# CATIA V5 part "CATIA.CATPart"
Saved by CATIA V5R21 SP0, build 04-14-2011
Part number: Part1
Bounding box of the stored display mesh (mm): x -76.2 to 76.2, y -75.042 to 75.042, z 0 to 0
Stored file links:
  C:\Users\Orange\Desktop\Sketcher-16\Documents\CATIA.CATPart
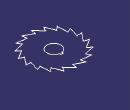
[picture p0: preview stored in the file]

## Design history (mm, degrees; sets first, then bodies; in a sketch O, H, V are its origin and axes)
Body1 (main body)
  Sketch1 on xy-plane, origin (0, 0, 0), H (1, 0, 0), V (0, 1, 0)
    arc A1 centre (0, 0) radius 19.05 from (-3.175, 18.7836) to (3.175, 18.7836) ccw
    line L1 (59.6705, 21.7183) -> (71.6046, 26.0619)
    line L2 (63.5, 0) -> (71.6046, 26.0619)
    line L3 (48.6438, 40.817) -> (58.3726, 48.9804)
    line L4 (59.6705, 21.7183) -> (58.3726, 48.9804)
    line L5 (31.75, 54.9926) -> (38.1, 65.9911)
    line L6 (48.6438, 40.817) -> (38.1, 65.9911)
    line L7 (11.0267, 62.5353) -> (13.232, 75.0424)
    line L8 (31.75, 54.9926) -> (13.232, 75.0424)
    line L9 (-11.0267, 62.5353) -> (-13.232, 75.0424)
    line L10 (11.0267, 62.5353) -> (-13.232, 75.0424)
    line L11 (-31.75, 54.9926) -> (-38.1, 65.9911)
    line L12 (-11.0267, 62.5353) -> (-38.1, 65.9911)
    line L13 (-48.6438, 40.817) -> (-58.3726, 48.9804)
    line L14 (-31.75, 54.9926) -> (-58.3726, 48.9804)
    line L15 (-59.6705, 21.7183) -> (-71.6046, 26.0619)
    line L16 (-48.6438, 40.817) -> (-71.6046, 26.0619)
    line L17 (-63.5, 0) -> (-76.2, 0)
    line L18 (-59.6705, 21.7183) -> (-76.2, 0)
    line L19 (-59.6705, -21.7183) -> (-71.6046, -26.0619)
    line L20 (-63.5, 0) -> (-71.6046, -26.0619)
    line L21 (-48.6438, -40.817) -> (-58.3726, -48.9804)
    line L22 (-59.6705, -21.7183) -> (-58.3726, -48.9804)
    line L23 (-31.75, -54.9926) -> (-38.1, -65.9911)
    line L24 (-48.6438, -40.817) -> (-38.1, -65.9911)
    line L25 (-11.0267, -62.5353) -> (-13.232, -75.0424)
    line L26 (-31.75, -54.9926) -> (-13.232, -75.0424)
    line L27 (11.0267, -62.5353) -> (13.232, -75.0424)
    line L28 (-11.0267, -62.5353) -> (13.232, -75.0424)
    line L29 (31.75, -54.9926) -> (38.1, -65.9911)
    line L30 (11.0267, -62.5353) -> (38.1, -65.9911)
    line L31 (48.6438, -40.817) -> (58.3726, -48.9804)
    line L32 (31.75, -54.9926) -> (58.3726, -48.9804)
    line L33 (59.6705, -21.7183) -> (71.6046, -26.0619)
    line L34 (48.6438, -40.817) -> (71.6046, -26.0619)
    line L35 (63.5, 0) -> (76.2, 0)
    line L36 (59.6705, -21.7183) -> (76.2, 0)
    line L37 (-3.175, 22.352) -> (3.175, 22.352)
    point P73 (0, 22.352)
    line L38 (3.175, 22.352) -> (3.175, 18.7836)
    line L39 (-3.175, 22.352) -> (-3.175, 18.7836)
